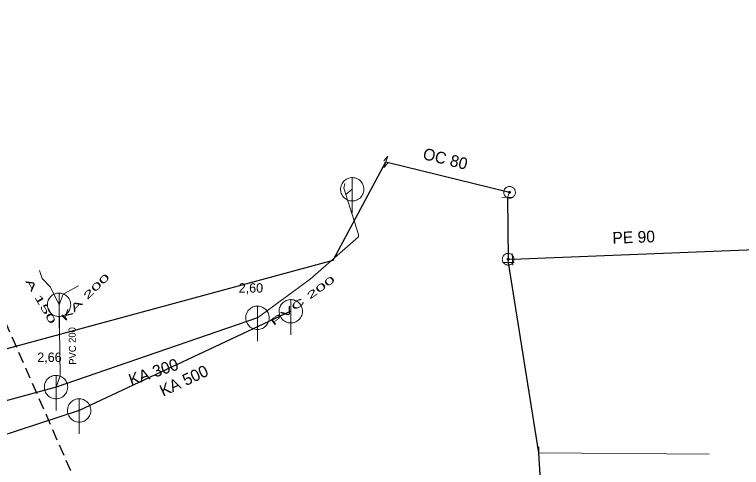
# Model space of a CAD drawing. Extents: x -693324 to -693034, y -967499 to -967236.
# Drawn here: x -693289.5 to -693227.3, y -967462.2 to -967423.4 of the extents above; entities that cross this region are included whole.
import ezdxf

# ---------------------------------------------------------------- set-up
doc = ezdxf.new("R2010")
doc.units = 0
doc.header["$LTSCALE"] = 0.32
doc.linetypes.add('MEDIUM_DASHED', pattern=[4.5, 3, -1.5])
doc.layers.add('1', color=7, linetype='Continuous')
for name, color, linetype, lineweight in [('11', 7, 'Continuous', 13), ('13', 7, 'Continuous', 13), ('14', 7, 'Continuous', 13), ('17', 7, 'Continuous', 25), ('22', 7, 'Continuous', 13), ('34', 7, 'Continuous', 13), ('47', 7, 'Continuous', 13), ('63', 7, 'MEDIUM_DASHED', 25)]:
    doc.layers.add(name, color=color, linetype=linetype, lineweight=lineweight)

msp = doc.modelspace()

# ---------------------------------------------------------------- linework, layer by layer
at = {"layer": '11'}
msp.add_line((-693260.581, -967438.37), (-693261.119, -967438.807), dxfattribs=at)
for points in [[(-693261.204, -967437.886), (-693261.287, -967438.263), (-693260.05, -967442.25), (-693260.056, -967442.423), (-693264.191, -967446.07), (-693268.686, -967449.357)], [(-693287.32, -967445.314), (-693287.09, -967446.006), (-693286.39, -967446.728), (-693285.655, -967448.249)], [(-693283.987, -967446.638), (-693285.309, -967447.348), (-693285.655, -967448.249)], [(-693285.655, -967448.249), (-693285.565, -967454.328), (-693285.912, -967455.287)]]:
    msp.add_lwpolyline(points, dxfattribs=at)
at = {"layer": '13'}
msp.add_line((-693244.616, -967460.901), (-693230.052, -967461.028), dxfattribs=at)
at = {"layer": '14'}
for p, q in [((-693247.129, -967438.629), (-693247.298, -967439.063)), ((-693247.247, -967444.351), (-693246.874, -967444.357)), ((-693247.247, -967444.351), (-693247.245, -967444.625)), ((-693244.666, -967460.901), (-693244.616, -967460.901))]:
    msp.add_line(p, q, dxfattribs=at)
at = {"layer": '14', "lineweight": 25}
for p, q in [((-693265.835, -967448.804), (-693283.932, -967457.285)), ((-693268.686, -967449.357), (-693285.912, -967455.287)), ((-693285.912, -967455.287), (-693320.811, -967464.93)), ((-693283.932, -967457.285), (-693321.666, -967469.651))]:
    msp.add_line(p, q, dxfattribs=at)
at = {"layer": '17'}
msp.add_line((-693247.298, -967439.063), (-693247.247, -967444.351), dxfattribs=at)
for points in [[(-693246.874, -967444.357), (-693224.688, -967443.46), (-693211.451, -967442.276), (-693204.217, -967441.27), (-693198.956, -967439.987), (-693188.493, -967436.306), (-693177.543, -967432.721), (-693167.835, -967429.64), (-693156.442, -967426.028), (-693152.732, -967424.739)], [(-693321.881, -967460.588), (-693262.219, -967444.421), (-693257.709, -967436.032), (-693247.129, -967438.629)], [(-693247.245, -967444.625), (-693244.666, -967460.901), (-693244.541, -967462.822), (-693244.585, -967463.638), (-693245.103, -967464.195), (-693246.853, -967465.098), (-693257.557, -967471.002), (-693257.767, -967471.145), (-693282.342, -967482.884), (-693285.493, -967484.813), (-693288.565, -967487.522)]]:
    msp.add_lwpolyline(points, dxfattribs=at)
at = {"layer": '22'}
for p, q in [((-693260.581, -967440.37), (-693260.58, -967437.37)), ((-693285.655, -967450.249), (-693285.654, -967447.249)), ((-693265.835, -967450.804), (-693265.834, -967447.804)), ((-693268.686, -967451.357), (-693268.685, -967448.357)), ((-693285.912, -967457.287), (-693285.911, -967454.287)), ((-693283.932, -967459.285), (-693283.931, -967456.285))]:
    msp.add_line(p, q, dxfattribs=at)
for points in [[(-693259.581, -967438.37), (-693259.586, -967438.261), (-693259.604, -967438.153), (-693259.634, -967438.047), (-693259.674, -967437.946), (-693259.726, -967437.849), (-693259.788, -967437.759), (-693259.86, -967437.676), (-693259.94, -967437.602), (-693260.028, -967437.536), (-693260.122, -967437.481), (-693260.222, -967437.436), (-693260.327, -967437.403), (-693260.434, -967437.381), (-693260.543, -967437.371), (-693260.653, -967437.373), (-693260.761, -967437.387), (-693260.868, -967437.412), (-693260.971, -967437.449), (-693261.069, -967437.498), (-693261.161, -967437.556), (-693261.247, -967437.625), (-693261.324, -967437.702), (-693261.393, -967437.788), (-693261.452, -967437.88), (-693261.5, -967437.978), (-693261.537, -967438.081), (-693261.563, -967438.188), (-693261.577, -967438.296), (-693261.58, -967438.406), (-693261.57, -967438.515), (-693261.549, -967438.622), (-693261.515, -967438.726), (-693261.471, -967438.826), (-693261.416, -967438.921), (-693261.35, -967439.009), (-693261.276, -967439.089), (-693261.193, -967439.161), (-693261.103, -967439.223), (-693261.007, -967439.275), (-693260.905, -967439.316), (-693260.8, -967439.346), (-693260.692, -967439.364), (-693260.582, -967439.37), (-693260.473, -967439.364), (-693260.365, -967439.346), (-693260.26, -967439.317), (-693260.158, -967439.276), (-693260.061, -967439.224), (-693259.971, -967439.162), (-693259.888, -967439.091), (-693259.813, -967439.011), (-693259.748, -967438.923), (-693259.692, -967438.829), (-693259.648, -967438.729), (-693259.614, -967438.625), (-693259.592, -967438.517), (-693259.582, -967438.408)], [(-693284.655, -967448.249), (-693284.66, -967448.14), (-693284.678, -967448.032), (-693284.708, -967447.926), (-693284.748, -967447.825), (-693284.8, -967447.728), (-693284.862, -967447.638), (-693284.934, -967447.555), (-693285.014, -967447.481), (-693285.102, -967447.415), (-693285.196, -967447.36), (-693285.296, -967447.315), (-693285.401, -967447.282), (-693285.508, -967447.26), (-693285.617, -967447.25), (-693285.727, -967447.252), (-693285.835, -967447.266), (-693285.942, -967447.291), (-693286.045, -967447.328), (-693286.143, -967447.377), (-693286.235, -967447.435), (-693286.321, -967447.504), (-693286.398, -967447.581), (-693286.467, -967447.667), (-693286.526, -967447.759), (-693286.574, -967447.857), (-693286.611, -967447.96), (-693286.637, -967448.067), (-693286.651, -967448.175), (-693286.654, -967448.285), (-693286.644, -967448.394), (-693286.623, -967448.501), (-693286.589, -967448.605), (-693286.545, -967448.705), (-693286.49, -967448.8), (-693286.424, -967448.888), (-693286.35, -967448.968), (-693286.267, -967449.04), (-693286.177, -967449.102), (-693286.081, -967449.154), (-693285.979, -967449.195), (-693285.874, -967449.225), (-693285.766, -967449.243), (-693285.656, -967449.249), (-693285.547, -967449.243), (-693285.439, -967449.225), (-693285.334, -967449.196), (-693285.232, -967449.155), (-693285.135, -967449.103), (-693285.045, -967449.041), (-693284.962, -967448.97), (-693284.887, -967448.89), (-693284.822, -967448.802), (-693284.766, -967448.708), (-693284.722, -967448.608), (-693284.688, -967448.504), (-693284.666, -967448.396), (-693284.656, -967448.287)], [(-693264.835, -967448.804), (-693264.84, -967448.695), (-693264.858, -967448.587), (-693264.888, -967448.481), (-693264.928, -967448.38), (-693264.98, -967448.283), (-693265.042, -967448.193), (-693265.114, -967448.11), (-693265.194, -967448.036), (-693265.282, -967447.97), (-693265.376, -967447.915), (-693265.476, -967447.87), (-693265.581, -967447.837), (-693265.688, -967447.815), (-693265.797, -967447.805), (-693265.907, -967447.807), (-693266.015, -967447.821), (-693266.122, -967447.846), (-693266.225, -967447.883), (-693266.323, -967447.932), (-693266.415, -967447.99), (-693266.501, -967448.059), (-693266.578, -967448.136), (-693266.647, -967448.222), (-693266.706, -967448.314), (-693266.754, -967448.412), (-693266.791, -967448.515), (-693266.817, -967448.622), (-693266.831, -967448.73), (-693266.834, -967448.84), (-693266.824, -967448.949), (-693266.803, -967449.056), (-693266.769, -967449.16), (-693266.725, -967449.26), (-693266.67, -967449.355), (-693266.604, -967449.443), (-693266.53, -967449.523), (-693266.447, -967449.595), (-693266.357, -967449.657), (-693266.261, -967449.709), (-693266.159, -967449.75), (-693266.054, -967449.78), (-693265.946, -967449.798), (-693265.836, -967449.804), (-693265.727, -967449.798), (-693265.619, -967449.78), (-693265.514, -967449.751), (-693265.412, -967449.71), (-693265.315, -967449.658), (-693265.225, -967449.596), (-693265.142, -967449.525), (-693265.067, -967449.445), (-693265.002, -967449.357), (-693264.946, -967449.263), (-693264.902, -967449.163), (-693264.868, -967449.059), (-693264.846, -967448.951), (-693264.836, -967448.842)], [(-693267.686, -967449.357), (-693267.691, -967449.248), (-693267.709, -967449.14), (-693267.739, -967449.034), (-693267.779, -967448.933), (-693267.831, -967448.836), (-693267.893, -967448.746), (-693267.965, -967448.663), (-693268.045, -967448.589), (-693268.133, -967448.523), (-693268.227, -967448.468), (-693268.327, -967448.423), (-693268.432, -967448.39), (-693268.539, -967448.368), (-693268.648, -967448.358), (-693268.758, -967448.36), (-693268.866, -967448.374), (-693268.973, -967448.399), (-693269.076, -967448.436), (-693269.174, -967448.485), (-693269.266, -967448.543), (-693269.352, -967448.612), (-693269.429, -967448.689), (-693269.498, -967448.775), (-693269.557, -967448.867), (-693269.605, -967448.965), (-693269.642, -967449.068), (-693269.668, -967449.175), (-693269.682, -967449.283), (-693269.685, -967449.393), (-693269.675, -967449.502), (-693269.654, -967449.609), (-693269.62, -967449.713), (-693269.576, -967449.813), (-693269.521, -967449.908), (-693269.455, -967449.996), (-693269.381, -967450.076), (-693269.298, -967450.148), (-693269.208, -967450.21), (-693269.112, -967450.262), (-693269.01, -967450.303), (-693268.905, -967450.333), (-693268.797, -967450.351), (-693268.687, -967450.357), (-693268.578, -967450.351), (-693268.47, -967450.333), (-693268.365, -967450.304), (-693268.263, -967450.263), (-693268.166, -967450.211), (-693268.076, -967450.149), (-693267.993, -967450.078), (-693267.918, -967449.998), (-693267.853, -967449.91), (-693267.797, -967449.816), (-693267.753, -967449.716), (-693267.719, -967449.612), (-693267.697, -967449.504), (-693267.687, -967449.395)], [(-693284.912, -967455.287), (-693284.917, -967455.178), (-693284.935, -967455.07), (-693284.965, -967454.964), (-693285.005, -967454.863), (-693285.057, -967454.766), (-693285.119, -967454.676), (-693285.191, -967454.593), (-693285.271, -967454.519), (-693285.359, -967454.453), (-693285.453, -967454.398), (-693285.553, -967454.353), (-693285.658, -967454.32), (-693285.765, -967454.298), (-693285.874, -967454.288), (-693285.984, -967454.29), (-693286.092, -967454.304), (-693286.199, -967454.329), (-693286.302, -967454.366), (-693286.4, -967454.415), (-693286.492, -967454.473), (-693286.578, -967454.542), (-693286.655, -967454.619), (-693286.724, -967454.705), (-693286.783, -967454.797), (-693286.831, -967454.895), (-693286.868, -967454.998), (-693286.894, -967455.105), (-693286.908, -967455.213), (-693286.911, -967455.323), (-693286.901, -967455.432), (-693286.88, -967455.539), (-693286.846, -967455.643), (-693286.802, -967455.743), (-693286.747, -967455.838), (-693286.681, -967455.926), (-693286.607, -967456.006), (-693286.524, -967456.078), (-693286.434, -967456.14), (-693286.338, -967456.192), (-693286.236, -967456.233), (-693286.131, -967456.263), (-693286.023, -967456.281), (-693285.913, -967456.287), (-693285.804, -967456.281), (-693285.696, -967456.263), (-693285.591, -967456.234), (-693285.489, -967456.193), (-693285.392, -967456.141), (-693285.302, -967456.079), (-693285.219, -967456.008), (-693285.144, -967455.928), (-693285.079, -967455.84), (-693285.023, -967455.746), (-693284.979, -967455.646), (-693284.945, -967455.542), (-693284.923, -967455.434), (-693284.913, -967455.325)], [(-693282.932, -967457.285), (-693282.937, -967457.176), (-693282.955, -967457.068), (-693282.985, -967456.962), (-693283.025, -967456.861), (-693283.077, -967456.764), (-693283.139, -967456.674), (-693283.211, -967456.591), (-693283.291, -967456.517), (-693283.379, -967456.451), (-693283.473, -967456.396), (-693283.573, -967456.351), (-693283.678, -967456.318), (-693283.785, -967456.296), (-693283.894, -967456.286), (-693284.004, -967456.288), (-693284.112, -967456.302), (-693284.219, -967456.327), (-693284.322, -967456.364), (-693284.42, -967456.413), (-693284.512, -967456.471), (-693284.598, -967456.54), (-693284.675, -967456.617), (-693284.744, -967456.703), (-693284.803, -967456.795), (-693284.851, -967456.893), (-693284.888, -967456.996), (-693284.914, -967457.103), (-693284.928, -967457.211), (-693284.931, -967457.321), (-693284.921, -967457.43), (-693284.9, -967457.537), (-693284.866, -967457.641), (-693284.822, -967457.741), (-693284.767, -967457.836), (-693284.701, -967457.924), (-693284.627, -967458.004), (-693284.544, -967458.076), (-693284.454, -967458.138), (-693284.358, -967458.19), (-693284.256, -967458.231), (-693284.151, -967458.261), (-693284.043, -967458.279), (-693283.933, -967458.285), (-693283.824, -967458.279), (-693283.716, -967458.261), (-693283.611, -967458.232), (-693283.509, -967458.191), (-693283.412, -967458.139), (-693283.322, -967458.077), (-693283.239, -967458.006), (-693283.164, -967457.926), (-693283.099, -967457.838), (-693283.043, -967457.744), (-693282.999, -967457.644), (-693282.965, -967457.54), (-693282.943, -967457.432), (-693282.933, -967457.323)]]:
    msp.add_lwpolyline(points, close=True, dxfattribs=at)
at = {"layer": '34'}
for p, q in [((-693246.798, -967439.057), (-693247.797, -967439.067)), ((-693246.894, -967443.857), (-693246.854, -967444.856)), ((-693246.745, -967444.62), (-693247.744, -967444.628)), ((-693244.612, -967460.401), (-693244.62, -967461.4))]:
    msp.add_line(p, q, dxfattribs=at)
at = {"layer": '47'}
msp.add_line((-693257.541, -967435.55), (-693257.882, -967435.93), dxfattribs=at)
msp.add_lwpolyline([(-693257.541, -967435.55), (-693257.876, -967436.513), (-693257.535, -967436.133)], dxfattribs=at)
for points in [[(-693246.643, -967438.748), (-693246.633, -967438.696), (-693246.629, -967438.644), (-693246.63, -967438.592), (-693246.636, -967438.54), (-693246.648, -967438.489), (-693246.666, -967438.439), (-693246.689, -967438.393), (-693246.716, -967438.348), (-693246.747, -967438.306), (-693246.783, -967438.268), (-693246.822, -967438.233), (-693246.866, -967438.204), (-693246.911, -967438.178), (-693246.96, -967438.158), (-693247.009, -967438.143), (-693247.061, -967438.133), (-693247.113, -967438.129), (-693247.166, -967438.13), (-693247.217, -967438.136), (-693247.268, -967438.148), (-693247.318, -967438.166), (-693247.365, -967438.188), (-693247.41, -967438.215), (-693247.452, -967438.246), (-693247.489, -967438.283), (-693247.524, -967438.322), (-693247.554, -967438.365), (-693247.579, -967438.411), (-693247.599, -967438.46), (-693247.614, -967438.509), (-693247.624, -967438.561), (-693247.628, -967438.613), (-693247.628, -967438.666), (-693247.621, -967438.717), (-693247.609, -967438.768), (-693247.592, -967438.818), (-693247.57, -967438.865), (-693247.543, -967438.91), (-693247.511, -967438.952), (-693247.474, -967438.989), (-693247.435, -967439.024), (-693247.392, -967439.054), (-693247.346, -967439.079), (-693247.297, -967439.099), (-693247.248, -967439.114), (-693247.196, -967439.124), (-693247.144, -967439.128), (-693247.092, -967439.127), (-693247.04, -967439.121), (-693246.989, -967439.109), (-693246.939, -967439.092), (-693246.893, -967439.069), (-693246.848, -967439.042), (-693246.806, -967439.01), (-693246.768, -967438.974), (-693246.733, -967438.935), (-693246.704, -967438.892), (-693246.678, -967438.846), (-693246.658, -967438.797)], [(-693247.049, -967438.648), (-693247.047, -967438.639), (-693247.047, -967438.631), (-693247.047, -967438.623), (-693247.048, -967438.614), (-693247.05, -967438.606), (-693247.053, -967438.598), (-693247.056, -967438.59), (-693247.061, -967438.582), (-693247.066, -967438.576), (-693247.072, -967438.569), (-693247.079, -967438.564), (-693247.086, -967438.559), (-693247.093, -967438.555), (-693247.1, -967438.551), (-693247.109, -967438.549), (-693247.118, -967438.547), (-693247.126, -967438.547), (-693247.134, -967438.547), (-693247.143, -967438.548), (-693247.151, -967438.55), (-693247.159, -967438.553), (-693247.167, -967438.556), (-693247.175, -967438.561), (-693247.182, -967438.566), (-693247.188, -967438.572), (-693247.193, -967438.579), (-693247.198, -967438.586), (-693247.202, -967438.593), (-693247.206, -967438.6), (-693247.208, -967438.609), (-693247.21, -967438.618), (-693247.21, -967438.626), (-693247.21, -967438.634), (-693247.209, -967438.643), (-693247.207, -967438.651), (-693247.205, -967438.659), (-693247.201, -967438.667), (-693247.196, -967438.675), (-693247.191, -967438.682), (-693247.185, -967438.688), (-693247.178, -967438.693), (-693247.171, -967438.698), (-693247.164, -967438.702), (-693247.157, -967438.706), (-693247.148, -967438.708), (-693247.139, -967438.71), (-693247.131, -967438.71), (-693247.123, -967438.71), (-693247.114, -967438.709), (-693247.106, -967438.707), (-693247.098, -967438.705), (-693247.09, -967438.701), (-693247.082, -967438.696), (-693247.076, -967438.691), (-693247.069, -967438.685), (-693247.064, -967438.678), (-693247.059, -967438.671), (-693247.055, -967438.664), (-693247.051, -967438.657)], [(-693246.747, -967444.359), (-693246.749, -967444.307), (-693246.756, -967444.254), (-693246.769, -967444.204), (-693246.786, -967444.155), (-693246.81, -967444.107), (-693246.838, -967444.063), (-693246.87, -967444.023), (-693246.907, -967443.985), (-693246.946, -967443.951), (-693246.99, -967443.922), (-693247.036, -967443.897), (-693247.085, -967443.878), (-693247.135, -967443.863), (-693247.187, -967443.854), (-693247.238, -967443.851), (-693247.29, -967443.853), (-693247.343, -967443.86), (-693247.394, -967443.873), (-693247.442, -967443.89), (-693247.49, -967443.914), (-693247.534, -967443.942), (-693247.575, -967443.974), (-693247.613, -967444.011), (-693247.647, -967444.05), (-693247.675, -967444.094), (-693247.7, -967444.14), (-693247.72, -967444.189), (-693247.734, -967444.239), (-693247.743, -967444.291), (-693247.746, -967444.342), (-693247.744, -967444.394), (-693247.737, -967444.447), (-693247.725, -967444.498), (-693247.707, -967444.546), (-693247.683, -967444.594), (-693247.656, -967444.638), (-693247.624, -967444.679), (-693247.587, -967444.717), (-693247.547, -967444.751), (-693247.503, -967444.779), (-693247.457, -967444.804), (-693247.409, -967444.824), (-693247.358, -967444.838), (-693247.306, -967444.847), (-693247.255, -967444.85), (-693247.203, -967444.848), (-693247.15, -967444.841), (-693247.1, -967444.829), (-693247.051, -967444.811), (-693247.003, -967444.787), (-693246.959, -967444.76), (-693246.919, -967444.728), (-693246.881, -967444.691), (-693246.847, -967444.651), (-693246.818, -967444.607), (-693246.793, -967444.561), (-693246.774, -967444.513), (-693246.759, -967444.462), (-693246.75, -967444.41)], [(-693247.165, -967444.352), (-693247.164, -967444.343), (-693247.166, -967444.335), (-693247.168, -967444.327), (-693247.171, -967444.319), (-693247.175, -967444.311), (-693247.18, -967444.304), (-693247.185, -967444.296), (-693247.191, -967444.29), (-693247.197, -967444.285), (-693247.204, -967444.28), (-693247.212, -967444.276), (-693247.22, -967444.273), (-693247.228, -967444.271), (-693247.236, -967444.269), (-693247.245, -967444.269), (-693247.254, -967444.268), (-693247.262, -967444.27), (-693247.27, -967444.272), (-693247.278, -967444.275), (-693247.286, -967444.279), (-693247.293, -967444.284), (-693247.301, -967444.289), (-693247.307, -967444.295), (-693247.313, -967444.301), (-693247.317, -967444.308), (-693247.321, -967444.316), (-693247.324, -967444.324), (-693247.326, -967444.332), (-693247.328, -967444.34), (-693247.328, -967444.349), (-693247.329, -967444.358), (-693247.327, -967444.366), (-693247.325, -967444.374), (-693247.322, -967444.382), (-693247.318, -967444.39), (-693247.314, -967444.397), (-693247.308, -967444.405), (-693247.302, -967444.411), (-693247.296, -967444.417), (-693247.289, -967444.421), (-693247.281, -967444.425), (-693247.273, -967444.428), (-693247.265, -967444.43), (-693247.257, -967444.432), (-693247.248, -967444.432), (-693247.239, -967444.433), (-693247.231, -967444.431), (-693247.223, -967444.429), (-693247.215, -967444.426), (-693247.207, -967444.422), (-693247.2, -967444.418), (-693247.192, -967444.412), (-693247.186, -967444.406), (-693247.181, -967444.4), (-693247.176, -967444.393), (-693247.172, -967444.385), (-693247.169, -967444.377), (-693247.167, -967444.369), (-693247.165, -967444.361)]]:
    msp.add_lwpolyline(points, close=True, dxfattribs=at)
at = {"layer": '63'}
msp.add_lwpolyline([(-693215.442, -967470.355), (-693268.475, -967499.384), (-693268.475, -967499.384), (-693301.969, -967422.904), (-693301.969, -967422.904), (-693282.431, -967353.124), (-693282.431, -967353.124), (-693315.367, -967297.3), (-693315.367, -967297.3), (-693271.824, -967262.689), (-693271.824, -967262.689), (-693150.127, -967236.451), (-693150.127, -967236.451), (-693034.013, -967255.99), (-693034.013, -967255.99), (-693048.527, -967323.537), (-693048.527, -967323.537), (-693120.541, -967319.63), (-693120.541, -967319.63), (-693193.67, -967351.449), (-693193.67, -967351.449), (-693214.325, -967418.997), (-693214.325, -967418.997)], close=True, dxfattribs=at)

# ---------------------------------------------------------------- texts
at = {"layer": '1'}
for s, height, rotation, p in [('OC 80 ', 1, 346, (-693254.612, -967435.777)), ('PE 90 ', 1, 2, (-693238.318, -967443.024)), ('PVC 200 ', 0.6, 91, (-693284.187, -967453.367)), ('KA 300', 1, 19, (-693279.489, -967455.175)), ('KA 500', 1, 25, (-693276.757, -967456.114))]:
    msp.add_text(s, height=height, rotation=rotation, dxfattribs=at).set_placement(p)
at = {"layer": '1', "width": 2.05}
for s, rotation, p in [('KA 200', 44, (-693285.15, -967449.694)), ('A 150 ', 300, (-693288.561, -967446.233)), ('PVC 200 ', 36, (-693267.313, -967450.075))]:
    msp.add_text(s, height=0.6, rotation=rotation, dxfattribs=at).set_placement(p)
at = {"layer": '1'}
for s, p in [('2,60', (-693270.286, -967447.204)), ('2,66', (-693287.513, -967453.135))]:
    msp.add_text(s, height=0.8, dxfattribs=at).set_placement(p)

doc.saveas('drawing.dxf')
